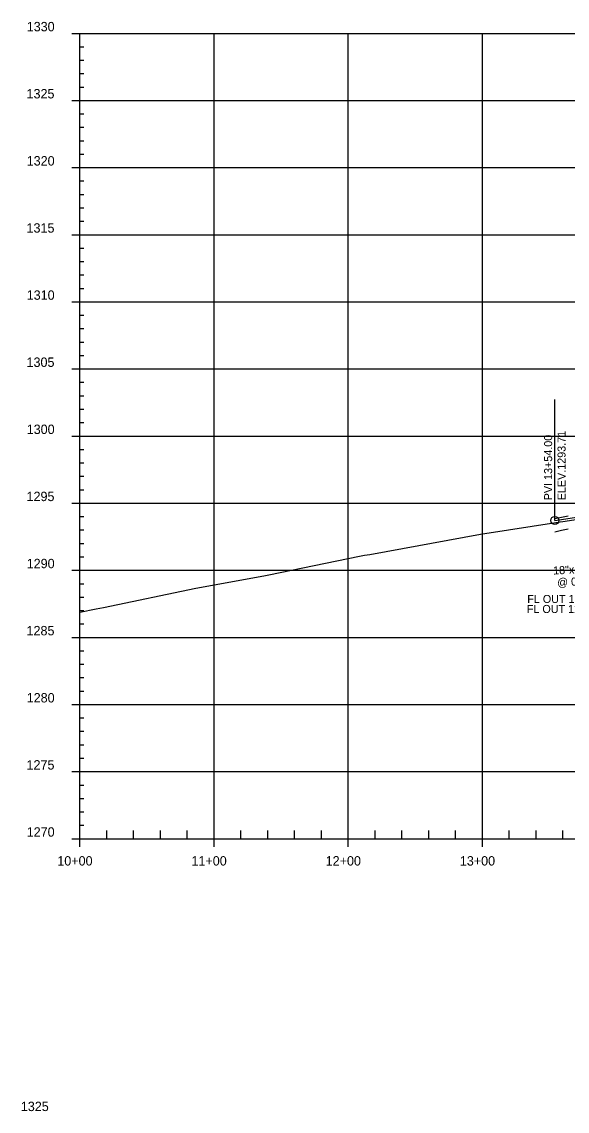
# Model space of a CAD drawing. Extents: x 670877 to 686811, y 705985 to 708501.
# Drawn here: x 684434 to 684841, y 707690 to 708501 of the extents above; entities that cross this region are included whole.
import ezdxf

# ---------------------------------------------------------------- set-up
doc = ezdxf.new("R2010")
doc.units = 0
for name, color, linetype in [('30', 7, 'Continuous'), ('37', 7, 'Continuous'), ('63', 7, 'Continuous'), ('Profile Drainage Annot Left', 7, 'Continuous'), ('Profile Drainage Annot Right', 7, 'Continuous'), ('R_Exist Surface', 7, 'Continuous'), ('R_Profile Work Left', 7, 'Continuous'), ('R_Profile Work Right', 7, 'Continuous'), ('R_Vert Alg', 7, 'Continuous'), ('R_Vert Alg Annot', 7, 'Continuous')]:
    doc.layers.add(name, color=color, linetype=linetype)

msp = doc.modelspace()

# ---------------------------------------------------------------- linework, layer by layer
at = {"layer": '37'}
for p, q in [((684471.28, 708492.85), (684477.28, 708492.85)), ((684477.28, 707892.85), (684477.28, 708492.85)), ((684477.28, 708492.85), (686777.28, 708492.85)), ((684577.28, 707892.85), (684577.28, 708492.85)), ((684677.28, 707892.85), (684677.28, 708492.85)), ((684777.28, 707892.85), (684777.28, 708492.85)), ((684477.28, 708482.85), (684480.28, 708482.85)), ((684477.28, 708472.85), (684480.28, 708472.85)), ((684477.28, 708462.85), (684480.28, 708462.85)), ((684477.28, 708452.85), (684480.28, 708452.85)), ((684471.28, 708442.85), (684477.28, 708442.85)), ((684477.28, 708442.85), (686777.28, 708442.85)), ((684477.28, 708432.85), (684480.28, 708432.85)), ((684477.28, 708422.85), (684480.28, 708422.85)), ((684477.28, 708412.85), (684480.28, 708412.85)), ((684477.28, 708402.85), (684480.28, 708402.85)), ((684471.28, 708392.85), (684477.28, 708392.85)), ((684477.28, 708392.85), (686777.28, 708392.85)), ((684477.28, 708382.85), (684480.28, 708382.85)), ((684477.28, 708372.85), (684480.28, 708372.85)), ((684477.28, 708362.85), (684480.28, 708362.85)), ((684477.28, 708352.85), (684480.28, 708352.85)), ((684471.28, 708342.85), (684477.28, 708342.85)), ((684477.28, 708342.85), (686777.28, 708342.85)), ((684477.28, 708332.85), (684480.28, 708332.85)), ((684477.28, 708322.85), (684480.28, 708322.85)), ((684477.28, 708312.85), (684480.28, 708312.85)), ((684477.28, 708302.85), (684480.28, 708302.85)), ((684471.28, 708292.85), (684477.28, 708292.85)), ((684477.28, 708292.85), (686777.28, 708292.85)), ((684477.28, 708282.85), (684480.28, 708282.85)), ((684477.28, 708272.85), (684480.28, 708272.85)), ((684477.28, 708262.85), (684480.28, 708262.85)), ((684477.28, 708252.85), (684480.28, 708252.85)), ((684471.28, 708242.85), (684477.28, 708242.85)), ((684477.28, 708242.85), (686777.28, 708242.85)), ((684477.28, 708232.85), (684480.28, 708232.85)), ((684477.28, 708222.85), (684480.28, 708222.85)), ((684477.28, 708212.85), (684480.28, 708212.85)), ((684477.28, 708202.85), (684480.28, 708202.85)), ((684471.28, 708192.85), (684477.28, 708192.85)), ((684477.28, 708192.85), (686777.28, 708192.85)), ((684477.28, 708182.85), (684480.28, 708182.85)), ((684477.28, 708172.85), (684480.28, 708172.85)), ((684477.28, 708162.85), (684480.28, 708162.85)), ((684477.28, 708152.85), (684480.28, 708152.85)), ((684471.28, 708142.85), (684477.28, 708142.85)), ((684477.28, 708142.85), (686777.28, 708142.85)), ((684477.28, 708132.85), (684480.28, 708132.85)), ((684477.28, 708122.85), (684480.28, 708122.85)), ((684477.28, 708112.85), (684480.28, 708112.85)), ((684477.28, 708102.85), (684480.28, 708102.85)), ((684471.28, 708092.85), (684477.28, 708092.85)), ((684477.28, 708092.85), (686777.28, 708092.85)), ((684477.28, 708082.85), (684480.28, 708082.85)), ((684477.28, 708072.85), (684480.28, 708072.85)), ((684477.28, 708062.85), (684480.28, 708062.85)), ((684477.28, 708052.85), (684480.28, 708052.85)), ((684471.28, 708042.85), (684477.28, 708042.85)), ((684477.28, 708042.85), (686777.28, 708042.85)), ((684477.28, 708032.85), (684480.28, 708032.85)), ((684477.28, 708022.85), (684480.28, 708022.85)), ((684477.28, 708012.85), (684480.28, 708012.85)), ((684477.28, 708002.85), (684480.28, 708002.85)), ((684471.28, 707992.85), (684477.28, 707992.85)), ((684477.28, 707992.85), (686777.28, 707992.85)), ((684477.28, 707982.85), (684480.28, 707982.85)), ((684477.28, 707972.85), (684480.28, 707972.85)), ((684477.28, 707962.85), (684480.28, 707962.85)), ((684477.28, 707952.85), (684480.28, 707952.85)), ((684471.28, 707942.85), (684477.28, 707942.85)), ((684477.28, 707942.85), (686777.28, 707942.85)), ((684477.28, 707932.85), (684480.28, 707932.85)), ((684477.28, 707922.85), (684480.28, 707922.85)), ((684477.28, 707912.85), (684480.28, 707912.85)), ((684477.28, 707902.85), (684480.28, 707902.85)), ((684497.28, 707892.85), (684497.28, 707898.85)), ((684517.28, 707892.85), (684517.28, 707898.85)), ((684537.28, 707892.85), (684537.28, 707898.85)), ((684557.28, 707892.85), (684557.28, 707898.85)), ((684597.28, 707892.85), (684597.28, 707898.85)), ((684617.28, 707892.85), (684617.28, 707898.85)), ((684637.28, 707892.85), (684637.28, 707898.85)), ((684657.28, 707892.85), (684657.28, 707898.85)), ((684697.28, 707892.85), (684697.28, 707898.85)), ((684717.28, 707892.85), (684717.28, 707898.85)), ((684737.28, 707892.85), (684737.28, 707898.85)), ((684757.28, 707892.85), (684757.28, 707898.85)), ((684797.28, 707892.85), (684797.28, 707898.85)), ((684817.28, 707892.85), (684817.28, 707898.85)), ((684837.28, 707892.85), (684837.28, 707898.85)), ((684471.28, 707892.85), (684477.28, 707892.85)), ((684477.28, 707892.85), (686777.28, 707892.85)), ((684477.28, 707886.85), (684477.28, 707892.85)), ((684577.28, 707886.85), (684577.28, 707892.85)), ((684677.28, 707886.85), (684677.28, 707892.85)), ((684777.28, 707886.85), (684777.28, 707892.85))]:
    msp.add_line(p, q, dxfattribs=at)
at = {"layer": 'R_Exist Surface'}
msp.add_lwpolyline([(684477.28, 708061.73), (684489.39, 708064.01), (684494.89, 708065.14), (684563.83, 708079.46), (684614.37, 708088.78), (684618.11, 708089.5), (684685.75, 708103.24), (684689.36, 708104), (684693.4, 708104.69), (684775.95, 708119.74), (684835.24, 708128.83), (684837.23, 708129.11), (684911.97, 708140.71)], dxfattribs=at)
at = {"layer": 'R_Profile Work Left'}
msp.add_lwpolyline([(684831.28, 708131.31), (684836.28, 708132.34), (684841.28, 708133.38)], dxfattribs=at)
at = {"layer": 'R_Profile Work Right'}
msp.add_lwpolyline([(684831.28, 708121.55), (684836.28, 708122.59), (684841.28, 708123.59)], dxfattribs=at)
at = {"layer": 'R_Vert Alg'}
msp.add_line((684831.28, 708129.95), (684906.28, 708141.65), dxfattribs=at)
msp.add_circle((684831.28, 708129.95), 3, dxfattribs=at)
at = {"layer": 'R_Vert Alg Annot'}
msp.add_line((684831.28, 708129.95), (684831.28, 708219.95), dxfattribs=at)

# ---------------------------------------------------------------- texts
at = {"layer": '30'}
for s, p in [('1330', (684437.66, 708494.35)), ('1325', (684437.54, 708444.35)), ('1320', (684437.66, 708394.35)), ('1315', (684437.54, 708344.35)), ('1310', (684437.66, 708294.35)), ('1305', (684437.54, 708244.35)), ('1300', (684437.66, 708194.35)), ('1295', (684437.54, 708144.35)), ('1290', (684437.66, 708094.35)), ('1285', (684437.54, 708044.35)), ('1280', (684437.66, 707994.35)), ('1275', (684437.54, 707944.35)), ('1270', (684437.66, 707894.35)), ('10+00', (684460.47, 707872.85)), ('11+00', (684560.47, 707872.85)), ('12+00', (684660.47, 707872.85)), ('13+00', (684760.47, 707872.85)), ('1325', (684433.29, 707689.93))]:
    msp.add_text(s, height=7, dxfattribs=at).set_placement(p)
at = {"layer": '63'}
msp.add_text('-', height=0.0001, dxfattribs=at).set_placement((684477.28, 707892.85))
msp.add_text('-', height=0.0001, dxfattribs=at).set_placement((684477.28, 707892.85))
at = {"layer": 'Profile Drainage Annot Left'}
for s, p in [('18"x 38\'', (684830.15, 708089.62)), ('@ 0.30%', (684833.15, 708080.76))]:
    msp.add_text(s, height=6, rotation=2.8769, dxfattribs=at).set_placement(p)
msp.add_text('FL OUT 1290.80', height=6, dxfattribs=at).set_placement((684810.74, 708068.45))
at = {"layer": 'Profile Drainage Annot Right'}
msp.add_text('FL OUT 1290.50', height=6, dxfattribs=at).set_placement((684810.42, 708061))
at = {"layer": 'R_Vert Alg Annot'}
for s, p in [('PVI 13+54.00', (684829.28, 708144.95)), ('ELEV.1293.71', (684839.28, 708144.95))]:
    msp.add_text(s, height=6, rotation=90, dxfattribs=at).set_placement(p)

doc.saveas('drawing.dxf')
